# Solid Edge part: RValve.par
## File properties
Author: ptcarter
Template: NORMMET.PAR
Last saved by: ptcarter
Revision: 33
Application: Solid Edge
Accuracy: 0.99
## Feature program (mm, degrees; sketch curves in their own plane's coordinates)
sketch for "unnamed RevolvedProtrusion 1" plane through (0, 0, 0) normal (0, 0, 1) x-axis (1, 0, 0)
  arc centre (0, 3.7054) radius 30 from (30, 3.7054) to (0, 33.7054) ccw
  line (0, 3.7054) -> (30, 3.7054)
revolve "unnamed RevolvedProtrusion 1" add finite 360 deg about sketch line (0, 3.7054) -> (0, 33.7054)
sketch for "unnamed Hole 1" plane through (0, 3.7054, 0) normal (0, -1, 0) x-axis (0, 0, 1)
  hole centre (0, 0) bore radius 15
hole "unnamed Hole 1" through
sketch for "unnamed Cutout 1" plane through (0, 0, 23) normal (0, 0, 1) x-axis (1, 0, 0)
  line (5.5902, 8.7054) -> (-5.5902, 8.7054)
  arc centre (0, 3.7054) radius 7.5 from (-7.5, 3.7054) to (-5.5902, 8.7054) cw
  line (-7.5, 3.7054) -> (7.5, 3.7054)
  arc centre (0, 3.7054) radius 7.5 from (5.5902, 8.7054) to (7.5, 3.7054) cw
extrude "unnamed Cutout 1" cut through along +normal
sketch for "unnamed Cutout 2" plane through (0, 3.7054, -0.4763) normal (0, -1, 0) x-axis (1, 0, 0)
extrude "unnamed Cutout 2" cut through along -normal
pattern "unnamed Pattern 1" of "unnamed Cutout 2"
extrude "unnamed Cutout 3" cut through
extrude "unnamed Cutout 4" cut through
extrude "unnamed Cutout 5" cut through
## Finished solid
Body 1: solid body, 11 faces, 22 edges, 8 vertices.
  Faces by surface: cylinder 7, plane 3, sphere 1
  Edges by curve: circle 12, line 6, intersection 4
Bounding box of the edges (mm; curved faces can reach further): 60.000 x 25.981 x 59.580, from (-30, 3.7054, -30) to (30, 29.6862, 29.5804).
Cylindrical faces by radius (mm): R1.5 x4, R7.5 x2, R15 x1
Spherical faces by radius (mm): R30 x1
Planar faces by outward normal: +z 1, -y 2
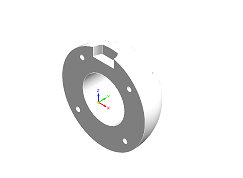
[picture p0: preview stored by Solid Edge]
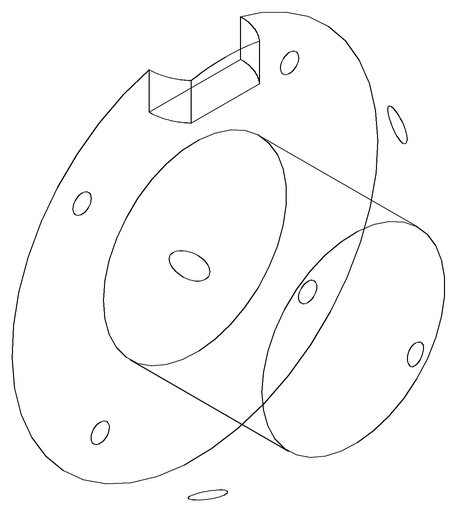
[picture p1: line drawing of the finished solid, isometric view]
